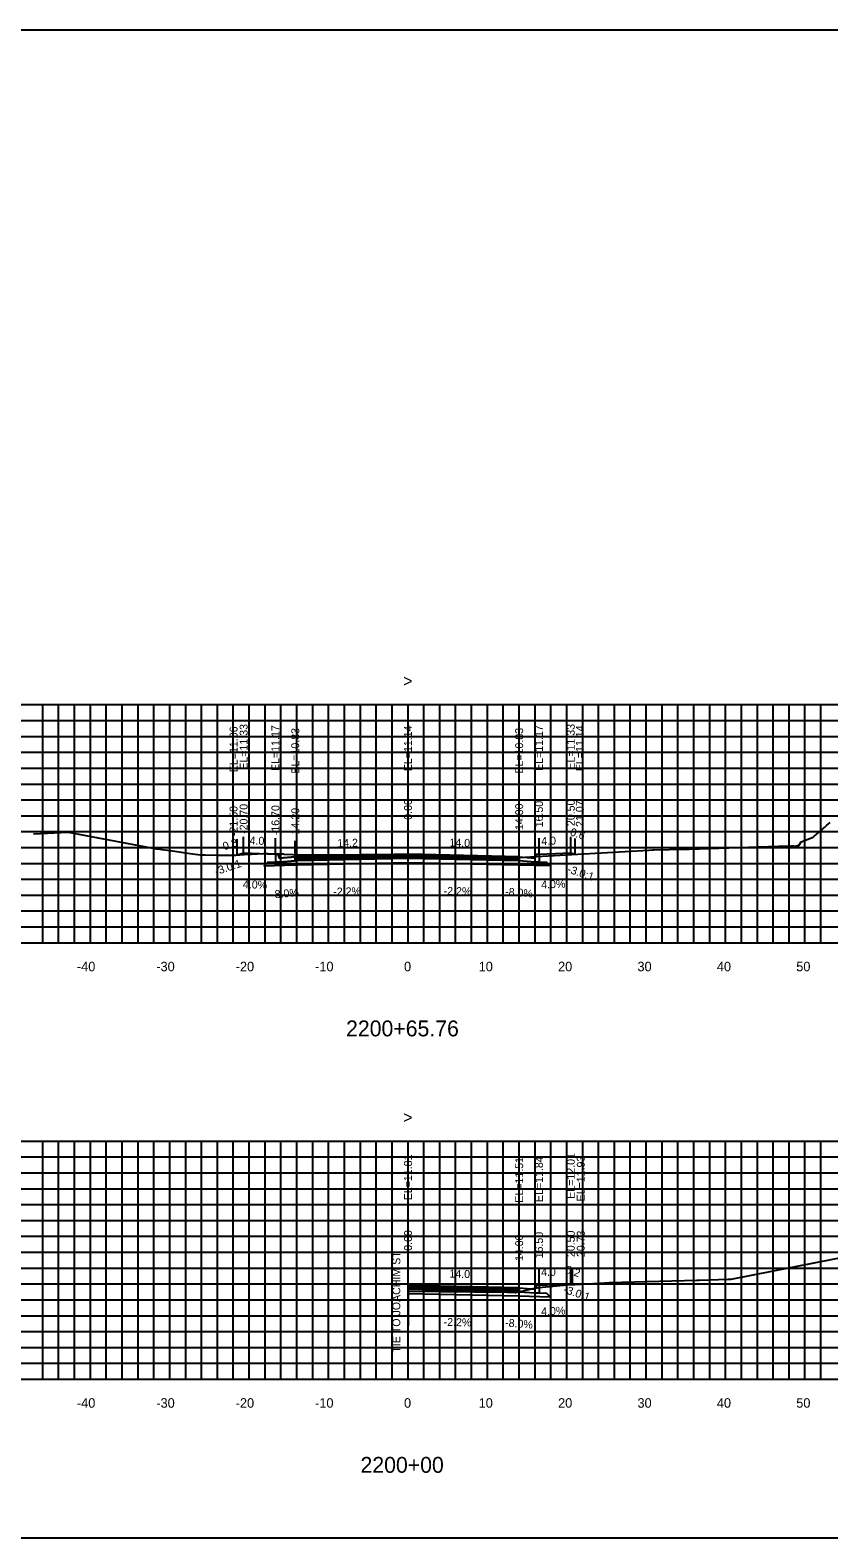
# Model space of a CAD drawing. Extents: x 1800624 to 1802445, y 250079 to 250269.
# Drawn here: x 1802243.4 to 1802344, y 250079.4 to 250269.4 of the extents above; entities that cross this region are included whole.
import ezdxf

# ---------------------------------------------------------------- set-up
doc = ezdxf.new("R2010")
doc.units = 0
for name, color, linetype in [('1', 7, 'Continuous'), ('10', 7, 'Continuous'), ('3', 7, 'Continuous'), ('4', 7, 'Continuous'), ('60', 7, 'Continuous'), ('BASE', 7, 'Continuous'), ('CL-CNST', 7, 'Continuous'), ('Level 62', 7, 'Continuous'), ('LOWER BINDER', 7, 'Continuous'), ('M-ROADS', 7, 'Continuous'), ('UPPER BINDER', 7, 'Continuous'), ('WEARING', 7, 'Continuous')]:
    doc.layers.add(name, color=color, linetype=linetype)

msp = doc.modelspace()

# ---------------------------------------------------------------- linework, layer by layer
for p, q in [((1802269.5, 250165.49), (1802269.5, 250167.49)), ((1802270.3, 250165.76), (1802270.3, 250167.76)), ((1802274.3, 250165.6), (1802274.3, 250167.6)), ((1802291, 250165.57), (1802291, 250167.57)), ((1802307.5, 250165.6), (1802307.5, 250167.6)), ((1802311.5, 250165.76), (1802311.5, 250167.76)), ((1802312.07, 250165.57), (1802312.07, 250167.57)), ((1802276.8, 250165.26), (1802276.8, 250167.26)), ((1802305, 250165.26), (1802305, 250167.26)), ((1802291, 250111.24), (1802291, 250113.24)), ((1802305, 250110.94), (1802305, 250112.94)), ((1802307.5, 250111.28), (1802307.5, 250113.28)), ((1802311.5, 250111.44), (1802311.5, 250113.44)), ((1802311.73, 250111.36), (1802311.73, 250113.36))]:
    msp.add_line(p, q)
for points in [[(1802141, 250079.43), (1802441, 250079.43), (1802441, 250269.43), (1802141, 250269.43)], [(1802276.8, 250165.26), (1802274.8, 250165.1), (1802274.63, 250165.6), (1802274.3, 250165.6), (1802274.3, 250164.57), (1802274.8, 250164.57), (1802276.8, 250164.73)], [(1802305, 250165.26), (1802307, 250165.1), (1802307.17, 250165.6), (1802307.5, 250165.6), (1802307.5, 250164.57), (1802307, 250164.57), (1802305, 250164.73)], [(1802305, 250110.94), (1802307, 250110.78), (1802307.17, 250111.28), (1802307.5, 250111.28), (1802307.5, 250110.25), (1802307, 250110.25), (1802305, 250110.41)]]:
    msp.add_lwpolyline(points, close=True)
at = {"layer": '3'}
msp.add_line((1802291, 250111.24), (1802291, 250106.14), dxfattribs=at)
at = {"layer": '60'}
for p, q in [((1802141, 250154.43), (1802441, 250154.43)), ((1802251, 250154.37), (1802251, 250154.43)), ((1802261, 250154.37), (1802261, 250154.43)), ((1802271, 250154.37), (1802271, 250154.43)), ((1802281, 250154.37), (1802281, 250154.43)), ((1802291, 250154.37), (1802291, 250154.43)), ((1802301, 250154.37), (1802301, 250154.43)), ((1802311, 250154.37), (1802311, 250154.43)), ((1802321, 250154.37), (1802321, 250154.43)), ((1802331, 250154.37), (1802331, 250154.43)), ((1802341, 250154.37), (1802341, 250154.43)), ((1802141, 250099.43), (1802441, 250099.43)), ((1802251, 250099.37), (1802251, 250099.43)), ((1802261, 250099.37), (1802261, 250099.43)), ((1802271, 250099.37), (1802271, 250099.43)), ((1802281, 250099.37), (1802281, 250099.43)), ((1802291, 250099.37), (1802291, 250099.43)), ((1802301, 250099.37), (1802301, 250099.43)), ((1802311, 250099.37), (1802311, 250099.43)), ((1802321, 250099.37), (1802321, 250099.43)), ((1802331, 250099.37), (1802331, 250099.43)), ((1802341, 250099.37), (1802341, 250099.43))]:
    msp.add_line(p, q, dxfattribs=at)
at = {"layer": 'BASE'}
for points in [[(1802305, 250164.23), (1802308.9, 250164.15), (1802308.5, 250164.55), (1802307.5, 250164.57), (1802307, 250164.57), (1802305, 250164.73), (1802291, 250165.04), (1802276.8, 250164.73), (1802274.8, 250164.57), (1802274.3, 250164.57), (1802273.3, 250164.55), (1802272.9, 250164.14), (1802276.8, 250164.23), (1802291, 250164.54)], [(1802305, 250109.91), (1802308.9, 250109.82), (1802308.5, 250110.22), (1802307.5, 250110.25), (1802307, 250110.25), (1802305, 250110.41), (1802291, 250110.71), (1802291, 250110.21)]]:
    msp.add_lwpolyline(points, close=True, dxfattribs=at)
at = {"layer": 'CL-CNST'}
for points in [[(1802269.5, 250165.49), (1802270.3, 250165.76), (1802274.3, 250165.6), (1802274.63, 250165.6), (1802274.8, 250165.1), (1802276.8, 250165.26), (1802291, 250165.57), (1802305, 250165.26), (1802307, 250165.1), (1802307.17, 250165.6), (1802307.5, 250165.6), (1802311.5, 250165.76), (1802312.07, 250165.57)], [(1802291, 250111.24), (1802305, 250110.94), (1802307, 250110.78), (1802307.17, 250111.28), (1802307.5, 250111.28), (1802311.5, 250111.44), (1802311.73, 250111.36)]]:
    msp.add_lwpolyline(points, dxfattribs=at)
at = {"layer": 'Level 62'}
for p, q in [((1802141, 250184.43), (1802441, 250184.43)), ((1802245, 250154.43), (1802245, 250184.43)), ((1802247, 250154.43), (1802247, 250184.43)), ((1802249, 250154.43), (1802249, 250184.43)), ((1802251, 250154.43), (1802251, 250184.43)), ((1802253, 250154.43), (1802253, 250184.43)), ((1802255, 250154.43), (1802255, 250184.43)), ((1802257, 250154.43), (1802257, 250184.43)), ((1802259, 250154.43), (1802259, 250184.43)), ((1802261, 250154.43), (1802261, 250184.43)), ((1802263, 250154.43), (1802263, 250184.43)), ((1802265, 250154.43), (1802265, 250184.43)), ((1802267, 250154.43), (1802267, 250184.43)), ((1802269, 250154.43), (1802269, 250184.43)), ((1802271, 250154.43), (1802271, 250184.43)), ((1802273, 250154.43), (1802273, 250184.43)), ((1802275, 250154.43), (1802275, 250184.43)), ((1802277, 250154.43), (1802277, 250184.43)), ((1802279, 250154.43), (1802279, 250184.43)), ((1802281, 250154.43), (1802281, 250184.43)), ((1802283, 250154.43), (1802283, 250184.43)), ((1802285, 250154.43), (1802285, 250184.43)), ((1802287, 250154.43), (1802287, 250184.43)), ((1802289, 250154.43), (1802289, 250184.43)), ((1802291, 250154.43), (1802291, 250184.43)), ((1802293, 250154.43), (1802293, 250184.43)), ((1802295, 250154.43), (1802295, 250184.43)), ((1802297, 250154.43), (1802297, 250184.43)), ((1802299, 250154.43), (1802299, 250184.43)), ((1802301, 250154.43), (1802301, 250184.43)), ((1802303, 250154.43), (1802303, 250184.43)), ((1802305, 250154.43), (1802305, 250184.43)), ((1802307, 250154.43), (1802307, 250184.43)), ((1802309, 250154.43), (1802309, 250184.43)), ((1802311, 250154.43), (1802311, 250184.43)), ((1802313, 250154.43), (1802313, 250184.43)), ((1802315, 250154.43), (1802315, 250184.43)), ((1802317, 250154.43), (1802317, 250184.43)), ((1802319, 250154.43), (1802319, 250184.43)), ((1802321, 250154.43), (1802321, 250184.43)), ((1802323, 250154.43), (1802323, 250184.43)), ((1802325, 250154.43), (1802325, 250184.43)), ((1802327, 250154.43), (1802327, 250184.43)), ((1802329, 250154.43), (1802329, 250184.43)), ((1802331, 250154.43), (1802331, 250184.43)), ((1802333, 250154.43), (1802333, 250184.43)), ((1802335, 250154.43), (1802335, 250184.43)), ((1802337, 250154.43), (1802337, 250184.43)), ((1802339, 250154.43), (1802339, 250184.43)), ((1802341, 250154.43), (1802341, 250184.43)), ((1802343, 250154.43), (1802343, 250184.43)), ((1802141, 250182.43), (1802441, 250182.43)), ((1802141, 250180.43), (1802441, 250180.43)), ((1802141, 250178.43), (1802441, 250178.43)), ((1802141, 250176.43), (1802441, 250176.43)), ((1802141, 250174.43), (1802441, 250174.43)), ((1802141, 250172.43), (1802441, 250172.43)), ((1802141, 250170.43), (1802441, 250170.43)), ((1802141, 250168.43), (1802441, 250168.43)), ((1802141, 250166.43), (1802441, 250166.43)), ((1802141, 250164.43), (1802441, 250164.43)), ((1802141, 250162.43), (1802441, 250162.43)), ((1802141, 250160.43), (1802441, 250160.43)), ((1802141, 250158.43), (1802441, 250158.43)), ((1802141, 250156.43), (1802441, 250156.43)), ((1802141, 250154.43), (1802441, 250154.43)), ((1802141, 250129.43), (1802441, 250129.43)), ((1802245, 250099.43), (1802245, 250129.43)), ((1802247, 250099.43), (1802247, 250129.43)), ((1802249, 250099.43), (1802249, 250129.43)), ((1802251, 250099.43), (1802251, 250129.43)), ((1802253, 250099.43), (1802253, 250129.43)), ((1802255, 250099.43), (1802255, 250129.43)), ((1802257, 250099.43), (1802257, 250129.43)), ((1802259, 250099.43), (1802259, 250129.43)), ((1802261, 250099.43), (1802261, 250129.43)), ((1802263, 250099.43), (1802263, 250129.43)), ((1802265, 250099.43), (1802265, 250129.43)), ((1802267, 250099.43), (1802267, 250129.43)), ((1802269, 250099.43), (1802269, 250129.43)), ((1802271, 250099.43), (1802271, 250129.43)), ((1802273, 250099.43), (1802273, 250129.43)), ((1802275, 250099.43), (1802275, 250129.43)), ((1802277, 250099.43), (1802277, 250129.43)), ((1802279, 250099.43), (1802279, 250129.43)), ((1802281, 250099.43), (1802281, 250129.43)), ((1802283, 250099.43), (1802283, 250129.43)), ((1802285, 250099.43), (1802285, 250129.43)), ((1802287, 250099.43), (1802287, 250129.43)), ((1802289, 250099.43), (1802289, 250129.43)), ((1802291, 250099.43), (1802291, 250129.43)), ((1802293, 250099.43), (1802293, 250129.43)), ((1802295, 250099.43), (1802295, 250129.43)), ((1802297, 250099.43), (1802297, 250129.43)), ((1802299, 250099.43), (1802299, 250129.43)), ((1802301, 250099.43), (1802301, 250129.43)), ((1802303, 250099.43), (1802303, 250129.43)), ((1802305, 250099.43), (1802305, 250129.43)), ((1802307, 250099.43), (1802307, 250129.43)), ((1802309, 250099.43), (1802309, 250129.43)), ((1802311, 250099.43), (1802311, 250129.43)), ((1802313, 250099.43), (1802313, 250129.43)), ((1802315, 250099.43), (1802315, 250129.43)), ((1802317, 250099.43), (1802317, 250129.43)), ((1802319, 250099.43), (1802319, 250129.43)), ((1802321, 250099.43), (1802321, 250129.43)), ((1802323, 250099.43), (1802323, 250129.43)), ((1802325, 250099.43), (1802325, 250129.43)), ((1802327, 250099.43), (1802327, 250129.43)), ((1802329, 250099.43), (1802329, 250129.43)), ((1802331, 250099.43), (1802331, 250129.43)), ((1802333, 250099.43), (1802333, 250129.43)), ((1802335, 250099.43), (1802335, 250129.43)), ((1802337, 250099.43), (1802337, 250129.43)), ((1802339, 250099.43), (1802339, 250129.43)), ((1802341, 250099.43), (1802341, 250129.43)), ((1802343, 250099.43), (1802343, 250129.43)), ((1802141, 250127.43), (1802441, 250127.43)), ((1802141, 250125.43), (1802441, 250125.43)), ((1802141, 250123.43), (1802441, 250123.43)), ((1802141, 250121.43), (1802441, 250121.43)), ((1802141, 250119.43), (1802441, 250119.43)), ((1802141, 250117.43), (1802441, 250117.43)), ((1802141, 250115.43), (1802441, 250115.43)), ((1802141, 250113.43), (1802441, 250113.43)), ((1802141, 250111.43), (1802441, 250111.43)), ((1802141, 250109.43), (1802441, 250109.43)), ((1802141, 250107.43), (1802441, 250107.43)), ((1802141, 250105.43), (1802441, 250105.43)), ((1802141, 250103.43), (1802441, 250103.43)), ((1802141, 250101.43), (1802441, 250101.43)), ((1802141, 250099.43), (1802441, 250099.43))]:
    msp.add_line(p, q, dxfattribs=at)
at = {"layer": 'LOWER BINDER'}
for points in [[(1802276.8, 250164.73), (1802276.8, 250164.92), (1802291, 250165.23), (1802305, 250164.92), (1802305, 250164.73), (1802291, 250165.04)], [(1802291, 250110.9), (1802305, 250110.6), (1802305, 250110.41), (1802291, 250110.71)]]:
    msp.add_lwpolyline(points, close=True, dxfattribs=at)
at = {"layer": 'M-ROADS'}
for points in [[(1802243.82, 250168.16), (1802248.21, 250168.35), (1802259.31, 250166.27), (1802259.32, 250166.28), (1802259.35, 250166.28), (1802259.4, 250166.26), (1802259.4, 250166.26), (1802261.33, 250165.99), (1802263.29, 250165.72), (1802264.81, 250165.51), (1802265.02, 250165.5), (1802265.46, 250165.49), (1802266.94, 250165.45), (1802267.38, 250165.45), (1802268.88, 250165.45), (1802269.32, 250165.48), (1802269.33, 250165.48), (1802270.85, 250165.58), (1802271.29, 250165.61), (1802272.82, 250165.69), (1802273.26, 250165.68), (1802273.3, 250165.68), (1802273.34, 250165.68), (1802274.84, 250165.65), (1802275.27, 250165.62), (1802275.33, 250165.62), (1802275.35, 250165.61), (1802276.5, 250165.53), (1802276.8, 250165.51), (1802276.8, 250165.51), (1802276.81, 250165.51), (1802277.86, 250165.51), (1802278.2, 250165.52), (1802291.66, 250165.58), (1802291.94, 250165.57), (1802292.11, 250165.57), (1802300.24, 250165.27), (1802301.92, 250165.23), (1802305, 250165.15), (1802306.43, 250165.25), (1802321.32, 250166.11), (1802321.8, 250166.12), (1802321.96, 250166.12), (1802325.85, 250166.23), (1802325.99, 250166.23), (1802326.43, 250166.23), (1802337.68, 250166.6), (1802338.18, 250166.61), (1802339.2, 250166.65), (1802339.57, 250166.65), (1802339.81, 250166.6), (1802340.06, 250166.67), (1802340.24, 250166.7), (1802340.53, 250167.14), (1802342.01, 250167.72), (1802342.1, 250167.81), (1802342.17, 250167.87), (1802342.21, 250167.9), (1802342.32, 250168), (1802342.46, 250168.11), (1802342.61, 250168.24), (1802342.77, 250168.38), (1802342.97, 250168.55), (1802343.19, 250168.74), (1802343.34, 250168.87), (1802343.46, 250168.97), (1802343.77, 250169.24), (1802344.15, 250169.57)], [(1802291, 250110.53), (1802303.44, 250110.4), (1802304.49, 250110.35), (1802304.56, 250110.35), (1802305.7, 250110.62), (1802306.92, 250110.9), (1802306.96, 250110.91), (1802307.26, 250110.95), (1802307.46, 250110.99), (1802307.48, 250110.99), (1802311.45, 250111.36), (1802312.01, 250111.36), (1802315.8, 250111.58), (1802316.16, 250111.58), (1802316.39, 250111.59), (1802327.38, 250111.91), (1802327.72, 250111.92), (1802331.33, 250112.01), (1802331.63, 250112.01), (1802331.71, 250112.01), (1802368.18, 250119.22)]]:
    msp.add_lwpolyline(points, dxfattribs=at)
at = {"layer": 'UPPER BINDER'}
for points in [[(1802276.8, 250164.92), (1802276.8, 250165.11), (1802291, 250165.42), (1802305, 250165.11), (1802305, 250164.92), (1802291, 250165.23)], [(1802291, 250111.09), (1802305, 250110.79), (1802305, 250110.6), (1802291, 250110.9)]]:
    msp.add_lwpolyline(points, close=True, dxfattribs=at)
at = {"layer": 'WEARING'}
for points in [[(1802305, 250165.11), (1802305, 250165.26), (1802291, 250165.57), (1802276.8, 250165.26), (1802276.8, 250165.11), (1802291, 250165.42)], [(1802305, 250110.79), (1802305, 250110.94), (1802291, 250111.24), (1802291, 250111.09)]]:
    msp.add_lwpolyline(points, close=True, dxfattribs=at)

# ---------------------------------------------------------------- texts
for rotation, p in [(18.4349, (1802266.86, 250162.93)), (341.5651, (1802310.99, 250163.3)), (341.5651, (1802310.49, 250110.34))]:
    msp.add_text('-3.0:1', height=1, rotation=rotation).set_placement(p)
at = {"layer": '1'}
for s, p in [('2200+65.76', (1802283.2, 250142.63)), ('2200+00', (1802285.02, 250087.63))]:
    msp.add_text(s, height=2, dxfattribs=at).set_placement(p)
at = {"layer": '10'}
for s, p in [('-40', (1802249.3, 250150.83)), ('-30', (1802259.3, 250150.83)), ('-20', (1802269.3, 250150.83)), ('-10', (1802279.3, 250150.83)), ('0', (1802290.5, 250150.83)), ('10', (1802299.9, 250150.83)), ('20', (1802309.9, 250150.83)), ('30', (1802319.9, 250150.83)), ('40', (1802329.9, 250150.83)), ('50', (1802339.9, 250150.83)), ('-40', (1802249.3, 250095.83)), ('-30', (1802259.3, 250095.83)), ('-20', (1802269.3, 250095.83)), ('-10', (1802279.3, 250095.83)), ('0', (1802290.5, 250095.83)), ('10', (1802299.9, 250095.83)), ('20', (1802309.9, 250095.83)), ('30', (1802319.9, 250095.83)), ('40', (1802329.9, 250095.83)), ('50', (1802339.9, 250095.83))]:
    msp.add_text(s, height=1.2, dxfattribs=at).set_placement(p)
at = {"layer": '3'}
for s, p in [('EL=11.06', (1802269.53, 250175.92)), ('EL=11.33', (1802270.8, 250176.23)), ('EL=11.17', (1802274.8, 250176.07)), ('EL=10.83', (1802277.3, 250175.73)), ('EL=11.14', (1802291.5, 250176.04)), ('EL=10.83', (1802305.5, 250175.74)), ('EL=11.17', (1802308, 250176.08)), ('EL=11.33', (1802312, 250176.24)), ('EL=11.14', (1802313.14, 250176.05)), ('-21.50', (1802269.53, 250167.87)), ('-20.70', (1802270.8, 250168.14)), ('-16.70', (1802274.8, 250167.98)), ('-14.20', (1802277.3, 250167.64)), ('0.00', (1802291.5, 250169.93)), ('14.00', (1802305.5, 250168.63)), ('16.50', (1802308, 250168.97)), ('20.50', (1802312, 250169.13)), ('21.07', (1802313.14, 250169.02)), ('EL=11.81', (1802291.5, 250121.97)), ('EL=11.84', (1802308, 250121.75)), ('EL=12.01', (1802312, 250122.16)), ('EL=11.93', (1802313.26, 250121.83)), ('EL=11.51', (1802305.5, 250121.66)), ('0.00', (1802291.5, 250115.61)), ('16.50', (1802308, 250114.65)), ('20.50', (1802312, 250114.81)), ('20.73', (1802313.26, 250114.81)), ('14.00', (1802305.5, 250114.31)), ('TIE TO JOACHIM ST', (1802290.03, 250102.77))]:
    msp.add_text(s, height=1, rotation=90, dxfattribs=at).set_placement(p)
at = {"layer": '4'}
for s, rotation, p in [('0.8', 18.4349, (1802267.87, 250166.07)), ('4.0', 357.7094, (1802271.03, 250166.83)), ('14.2', 1.2603, (1802282.1, 250166.48)), ('14.0', 358.7397, (1802296.21, 250166.56)), ('4.0', 2.2906, (1802307.8, 250166.73)), ('0.6', 341.5651, (1802311.34, 250167.98)), ('4.0%', 357.7094, (1802270.19, 250161.32)), ('4.0%', 2.2906, (1802307.79, 250161.25)), ('-8.0%', 4.5739, (1802273.8, 250160)), ('-2.2%', 1.2603, (1802281.6, 250160.36)), ('-2.2%', 358.7397, (1802295.48, 250160.47)), ('-8.0%', 355.4261, (1802303.2, 250160.39)), ('14.0', 358.7397, (1802296.21, 250112.23)), ('4.0', 2.2906, (1802307.78, 250112.4)), ('0.2', 341.5651, (1802310.74, 250112.85)), ('4.0%', 2.2906, (1802307.79, 250107.46)), ('-2.2%', 358.7397, (1802295.48, 250106.15)), ('-8.0%', 355.4261, (1802303.2, 250106.07))]:
    msp.add_text(s, height=1, rotation=rotation, dxfattribs=at).set_placement(p)
at = {"layer": '60'}
for p in [(1802290.39, 250186.68), (1802290.39, 250131.68)]:
    msp.add_text('>', height=1.5, dxfattribs=at).set_placement(p)

doc.saveas('drawing.dxf')
